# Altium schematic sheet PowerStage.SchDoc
size 431 x 279 mm; Date: Not shown in title block; ApprovedBy: Not shown in title block; CheckedBy: Not shown in title block; Author: Not shown in title block; CompanyName: Not shown in title block; DrawnBy: Forest Fu; Engineer: Not shown in title block; Organization: Not shown in title block; Address1: Not shown in title block; Address2: Not shown in title block; Address3: Not shown in title block; Address4: Not shown in title block; DocumentNumber: 1; Revision: Use project parameter SCH_Rev; SheetNumber: 2; SheetTotal: 6; PageSetup: Record=PageOptions¦CenterHorizontal=True¦CenterVertical=True¦PrintScale=1.00¦XCorrection=1.00¦YCorrection=1.00¦PrintKind=0¦BorderSize=5000000¦LeftOffset=0¦BottomOffset=0¦Orientation=2¦PaperLength=1000¦PaperWidth=1000¦Scale=100¦PaperSource=15¦PrintQuality=600¦MediaType=1¦DitherType=10¦PaperKind=Letter¦PrintScaleMode=1
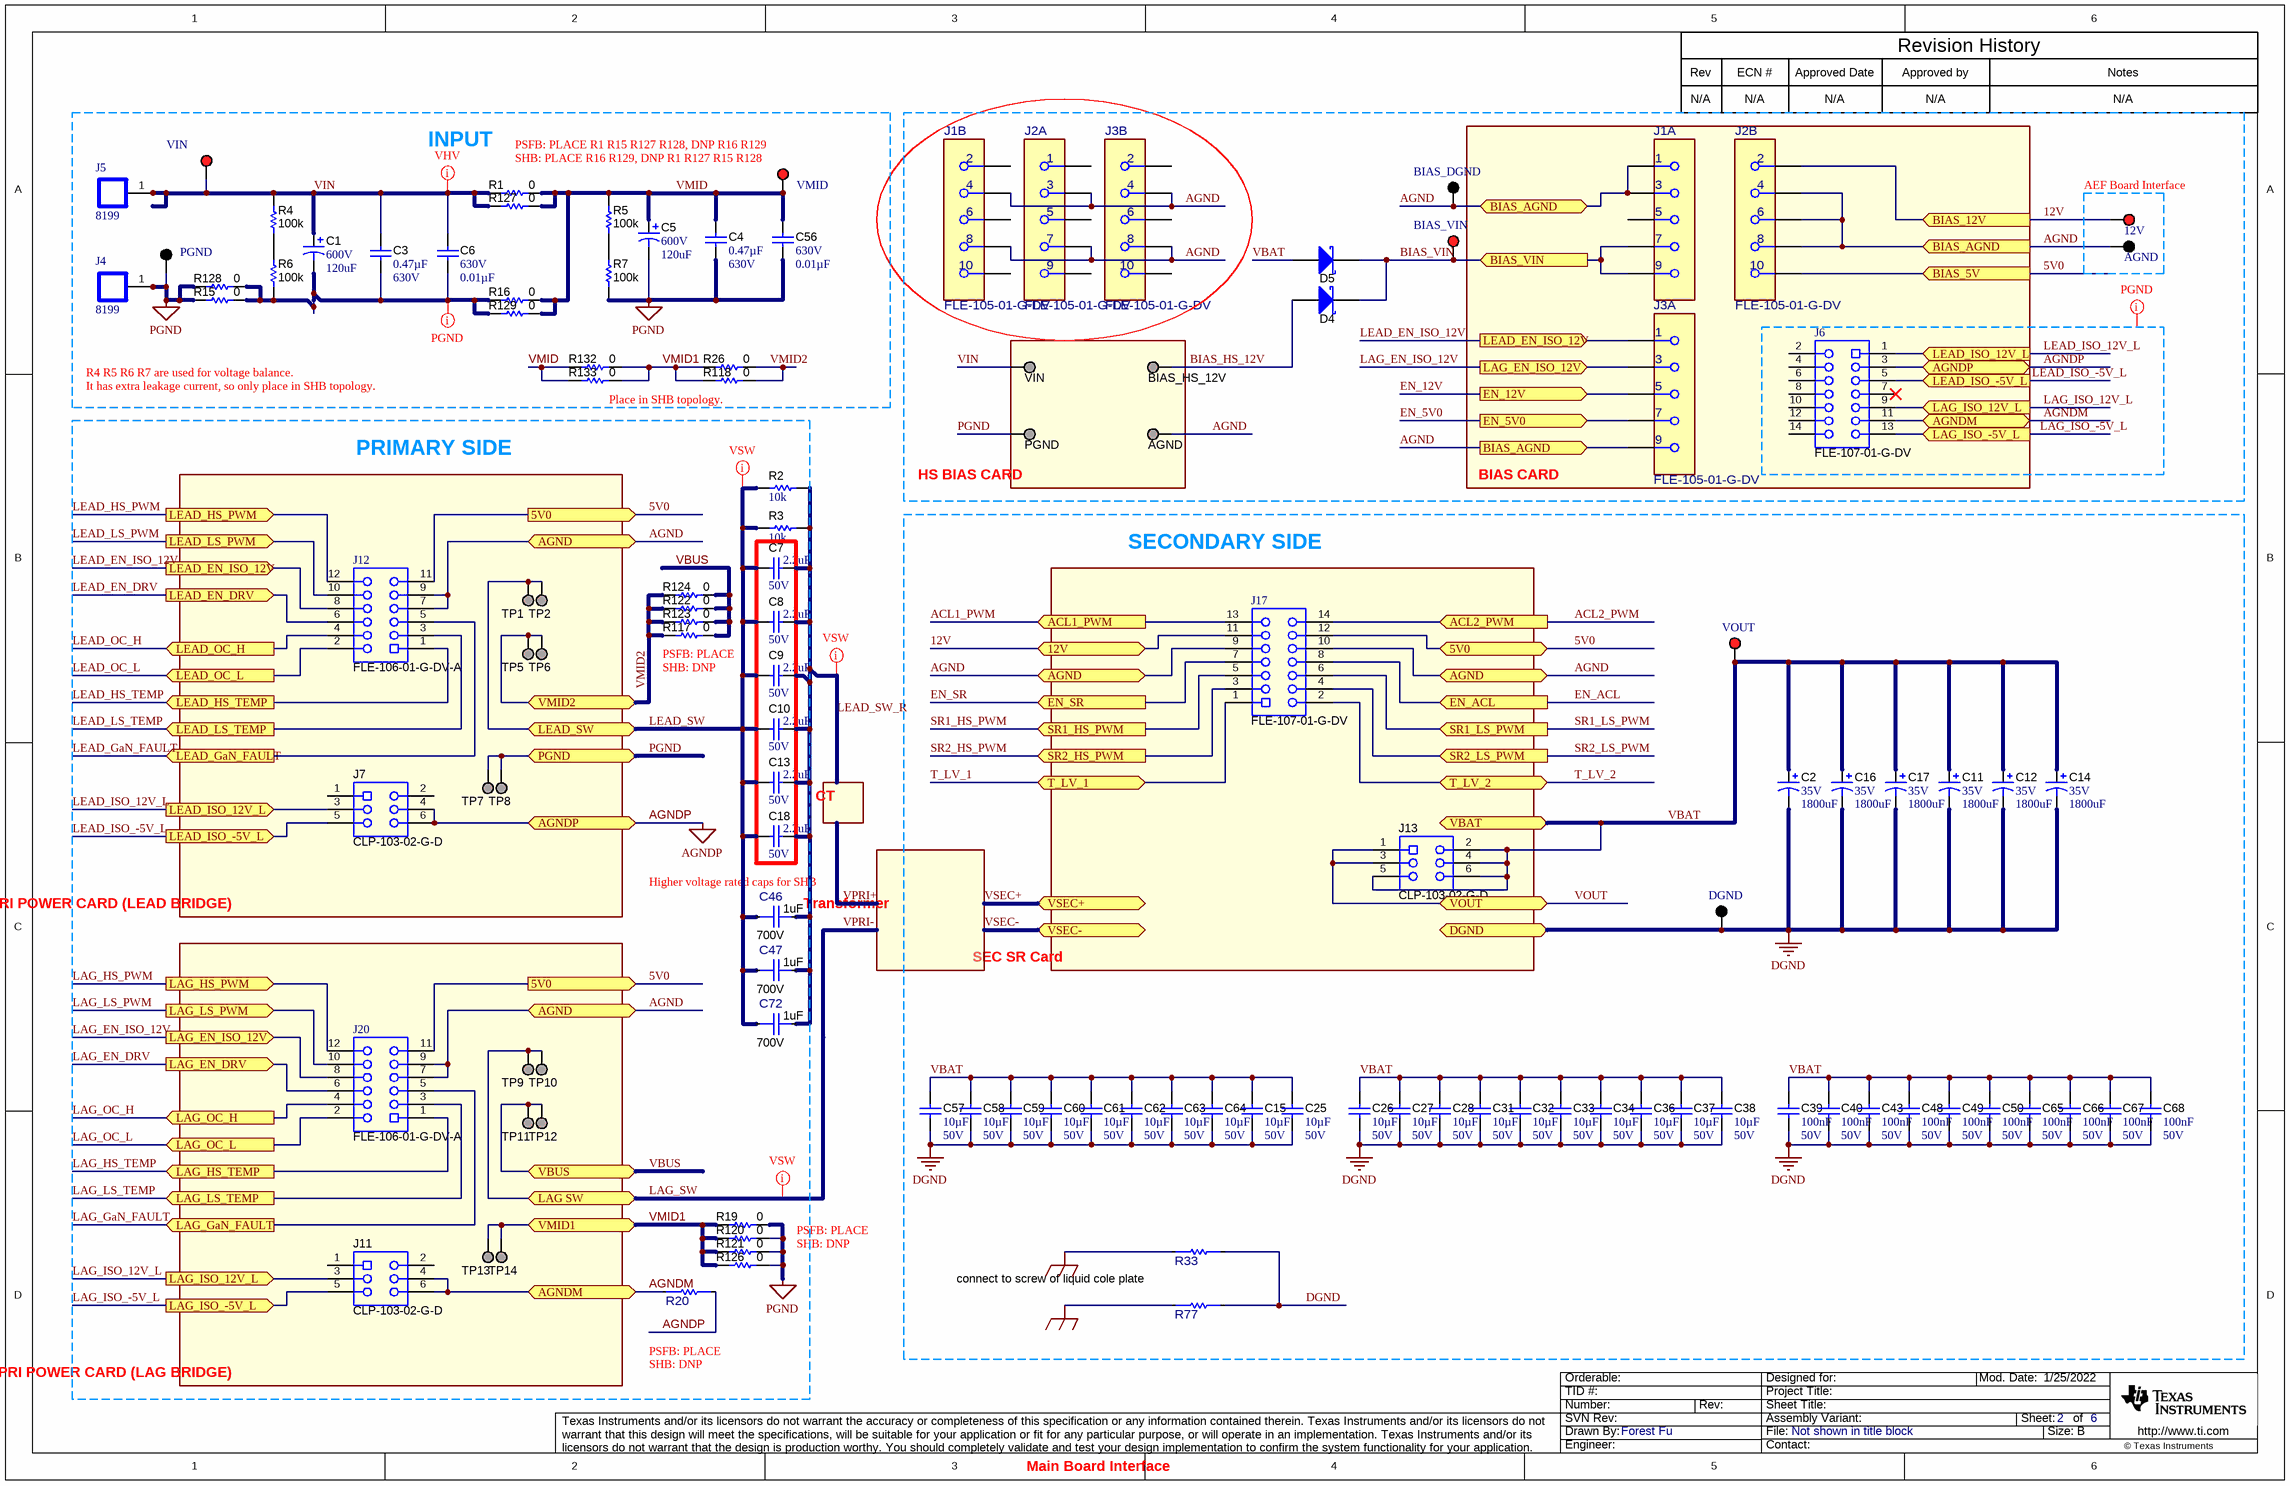
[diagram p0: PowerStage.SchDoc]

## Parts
(Parts that share a designator on the sheet are numbered #1, #2 ... from top to bottom, then left to right.)
12V  5000  [Keystone5000]  (value not drawn)
AGND#1  5001  [Keystone5001]  (value not drawn)
AGND#2  0312-0-15-15-34-27-10-0  [Mill-Max_0312-0-15-15-34-27-10-0]  (value not drawn)
BIAS_DGND  5001  [Keystone5001]  (value not drawn)
BIAS_HS_12V  0312-0-15-15-34-27-10-0  [Mill-Max_0312-0-15-15-34-27-10-0]  (value not drawn)
BIAS_VIN  5000  [Keystone5000]  (value not drawn)
C1  VDC_V: 600V  ValueDisplayed: 120uF  [Nichicon_3000x4500_Snap]  (hidden comment: LGN2X121MELB45)
C2  VDC_V: 35V  ValueDisplayed: 1800uF  [B41896_1600x3150]  (hidden comment: B41896C7188M000)
C3  ValueDisplayed: 0.47µF  VDC_V: 630V  [2220_280]  (hidden comment: CGA9P1X7T2J474M250KC)
C4  ValueDisplayed: 0.47µF  VDC_V: 630V  [2220_280]  (hidden comment: CGA9P1X7T2J474M250KC)
C5  VDC_V: 600V  ValueDisplayed: 120uF  [Nichicon_3000x4500_Snap]  (hidden comment: LGN2X121MELB45)
C6  VDC_V: 630V  ValueDisplayed: 0.01µF  [1210_150]  (hidden comment: CGA6J4C0G2J103J125AA)
C7  VDC_V: 50V  ValueDisplayed: 2.2uF  [1206_180]  (hidden comment: CGA5L3X7R1H225K160AB)
C8  VDC_V: 50V  ValueDisplayed: 2.2uF  [1206_180]  (hidden comment: CGA5L3X7R1H225K160AB)
C9  VDC_V: 50V  ValueDisplayed: 2.2uF  [1206_180]  (hidden comment: CGA5L3X7R1H225K160AB)
C10  VDC_V: 50V  ValueDisplayed: 2.2uF  [1206_180]  (hidden comment: CGA5L3X7R1H225K160AB)
C11  VDC_V: 35V  ValueDisplayed: 1800uF  [B41896_1600x3150]  (hidden comment: B41896C7188M000)
C12  VDC_V: 35V  ValueDisplayed: 1800uF  [B41896_1600x3150]  (hidden comment: B41896C7188M000)
C13  VDC_V: 50V  ValueDisplayed: 2.2uF  [1206_180]  (hidden comment: CGA5L3X7R1H225K160AB)
C14  VDC_V: 35V  ValueDisplayed: 1800uF  [B41896_1600x3150]  (hidden comment: B41896C7188M000)
C15  ValueDisplayed: 10µF  VDC_V: 50V  [1210_280]  (hidden comment: CGA6P3X7S1H106K250AE)
C16  VDC_V: 35V  ValueDisplayed: 1800uF  [B41896_1600x3150]  (hidden comment: B41896C7188M000)
C17  VDC_V: 35V  ValueDisplayed: 1800uF  [B41896_1600x3150]  (hidden comment: B41896C7188M000)
C18  VDC_V: 50V  ValueDisplayed: 2.2uF  [1206_180]  (hidden comment: CGA5L3X7R1H225K160AB)
C25  ValueDisplayed: 10µF  VDC_V: 50V  [1210_280]  (hidden comment: CGA6P3X7S1H106K250AE)
C26  ValueDisplayed: 10µF  VDC_V: 50V  [1210_280]  (hidden comment: CGA6P3X7S1H106K250AE)
C27  ValueDisplayed: 10µF  VDC_V: 50V  [1210_280]  (hidden comment: CGA6P3X7S1H106K250AE)
C28  ValueDisplayed: 10µF  VDC_V: 50V  [1210_280]  (hidden comment: CGA6P3X7S1H106K250AE)
C31  ValueDisplayed: 10µF  VDC_V: 50V  [1210_280]  (hidden comment: CGA6P3X7S1H106K250AE)
C32  ValueDisplayed: 10µF  VDC_V: 50V  [1210_280]  (hidden comment: CGA6P3X7S1H106K250AE)
C33  ValueDisplayed: 10µF  VDC_V: 50V  [1210_280]  (hidden comment: CGA6P3X7S1H106K250AE)
C34  ValueDisplayed: 10µF  VDC_V: 50V  [1210_280]  (hidden comment: CGA6P3X7S1H106K250AE)
C36  ValueDisplayed: 10µF  VDC_V: 50V  [1210_280]  (hidden comment: CGA6P3X7S1H106K250AE)
C37  ValueDisplayed: 10µF  VDC_V: 50V  [1210_280]  (hidden comment: CGA6P3X7S1H106K250AE)
C38  ValueDisplayed: 10µF  VDC_V: 50V  [1210_280]  (hidden comment: CGA6P3X7S1H106K250AE)
C39  Cap_F: 100nF  VDC_V: 50V  [0603]  (hidden comment: 06035C104KAZ2A)
C40  Cap_F: 100nF  VDC_V: 50V  [0603]  (hidden comment: 06035C104KAZ2A)
C43  Cap_F: 100nF  VDC_V: 50V  [0603]  (hidden comment: 06035C104KAZ2A)
C46  ValueDisplayed: 1uF  VDC_V: 700V  [FP-B58035U7105M052_SMD2-MFG]  (hidden comment: B58035U7105M052)
C47  ValueDisplayed: 1uF  VDC_V: 700V  [FP-B58035U7105M052_SMD2-MFG]  (hidden comment: B58035U7105M052)
C48  Cap_F: 100nF  VDC_V: 50V  [0603]  (hidden comment: 06035C104KAZ2A)
C49  Cap_F: 100nF  VDC_V: 50V  [0603]  (hidden comment: 06035C104KAZ2A)
C50  Cap_F: 100nF  VDC_V: 50V  [0603]  (hidden comment: 06035C104KAZ2A)
C56  VDC_V: 630V  ValueDisplayed: 0.01µF  [1210_150]  (hidden comment: CGA6J4C0G2J103J125AA)
C57  ValueDisplayed: 10µF  VDC_V: 50V  [1210_280]  (hidden comment: CGA6P3X7S1H106K250AE)
C58  ValueDisplayed: 10µF  VDC_V: 50V  [1210_280]  (hidden comment: CGA6P3X7S1H106K250AE)
C59  ValueDisplayed: 10µF  VDC_V: 50V  [1210_280]  (hidden comment: CGA6P3X7S1H106K250AE)
C60  ValueDisplayed: 10µF  VDC_V: 50V  [1210_280]  (hidden comment: CGA6P3X7S1H106K250AE)
C61  ValueDisplayed: 10µF  VDC_V: 50V  [1210_280]  (hidden comment: CGA6P3X7S1H106K250AE)
C62  ValueDisplayed: 10µF  VDC_V: 50V  [1210_280]  (hidden comment: CGA6P3X7S1H106K250AE)
C63  ValueDisplayed: 10µF  VDC_V: 50V  [1210_280]  (hidden comment: CGA6P3X7S1H106K250AE)
C64  ValueDisplayed: 10µF  VDC_V: 50V  [1210_280]  (hidden comment: CGA6P3X7S1H106K250AE)
C65  Cap_F: 100nF  VDC_V: 50V  [0603]  (hidden comment: 06035C104KAZ2A)
C66  Cap_F: 100nF  VDC_V: 50V  [0603]  (hidden comment: 06035C104KAZ2A)
C67  Cap_F: 100nF  VDC_V: 50V  [0603]  (hidden comment: 06035C104KAZ2A)
C68  Cap_F: 100nF  VDC_V: 50V  [0603]  (hidden comment: 06035C104KAZ2A)
C72  ValueDisplayed: 1uF  VDC_V: 700V  [FP-B58035U7105M052_SMD2-MFG]  (hidden comment: B58035U7105M052)
D4  FSV340AF  [SMAF]  (value not drawn)
D5  FSV340AF  [SMAF]  (value not drawn)
DGND  5001  [Keystone5001]  (value not drawn)
J1  FLE-105-01-G-DV  [FP-FLE-105-01-G-DV_HDR10-MFG]  (value not drawn)  (parts A,B of 2)
J2  FLE-105-01-G-DV  [FP-FLE-105-01-G-DV_HDR10-MFG]  (parts A,B of 2)
J3  FLE-105-01-G-DV  [FP-FLE-105-01-G-DV_HDR10-MFG]  (parts A,B of 2)
J4  8199  [SCREW_TERMINAL_8199]
J5  8199  [SCREW_TERMINAL_8199]
J6  FLE-107-01-G-DV  [Samtec_FLE-107-01-x-DV]
J7  CLP-103-02-G-D  [Samtec_CLP-103-02-x-D]
J11  CLP-103-02-G-D  [Samtec_CLP-103-02-x-D]
J12  FLE-106-01-G-DV-A  [Samtec_FLE-106-01-x-DV-A]
J13  CLP-103-02-G-D  [Samtec_CLP-103-02-x-D]
J17  FLE-107-01-G-DV  [Samtec_FLE-107-01-x-DV]
J20  FLE-106-01-G-DV-A  [Samtec_FLE-106-01-x-DV-A]
PGND#1  5001  [Keystone5001]  (value not drawn)
PGND#2  0312-0-15-15-34-27-10-0  [Mill-Max_0312-0-15-15-34-27-10-0]  (value not drawn)
R1  ValueDisplayed: 0  [2512]  (hidden comment: RMC1JPTE)
R2  ValueDisplayed: 10k  [1206L]  (hidden comment: CRCW120610K0JNEA)
R3  ValueDisplayed: 10k  [1206L]  (hidden comment: CRCW120610K0JNEA)
R4  ValueDisplayed: 100k  [1206]  (hidden comment: CRCW1206100KJNEA)
R5  ValueDisplayed: 100k  [1206]  (hidden comment: CRCW1206100KJNEA)
R6  ValueDisplayed: 100k  [1206]  (hidden comment: CRCW1206100KJNEA)
R7  ValueDisplayed: 100k  [1206]  (hidden comment: CRCW1206100KJNEA)
R15  ValueDisplayed: 0  [2512]  (hidden comment: RMC1JPTE)
R16  ValueDisplayed: 0  [2512]  (hidden comment: RMC1JPTE)
R19  ValueDisplayed: 0  [2512]  (hidden comment: RMC1JPTE)
R20  RMCF1206ZT0R00  [FP-RMCF1206ZT0R00_1206-MFG]  (value not drawn)
R26  ValueDisplayed: 0  [2512]  (hidden comment: RMC1JPTE)
R33  RMCF1206ZT0R00  [FP-RMCF1206ZT0R00_1206-MFG]  (value not drawn)
R77  RMCF1206ZT0R00  [FP-RMCF1206ZT0R00_1206-MFG]  (value not drawn)
R117  ValueDisplayed: 0  [2512]  (hidden comment: RMC1JPTE)
R118  ValueDisplayed: 0  [2512]  (hidden comment: RMC1JPTE)
R120  ValueDisplayed: 0  [2512]  (hidden comment: RMC1JPTE)
R121  ValueDisplayed: 0  [2512]  (hidden comment: RMC1JPTE)
R122  ValueDisplayed: 0  [2512]  (hidden comment: RMC1JPTE)
R123  ValueDisplayed: 0  [2512]  (hidden comment: RMC1JPTE)
R124  ValueDisplayed: 0  [2512]  (hidden comment: RMC1JPTE)
R126  ValueDisplayed: 0  [2512]  (hidden comment: RMC1JPTE)
R127  ValueDisplayed: 0  [2512]  (hidden comment: RMC1JPTE)
R128  ValueDisplayed: 0  [2512]  (hidden comment: RMC1JPTE)
R129  ValueDisplayed: 0  [2512]  (hidden comment: RMC1JPTE)
R132  ValueDisplayed: 0  [2512]  (hidden comment: RMC1JPTE)
R133  ValueDisplayed: 0  [2512]  (hidden comment: RMC1JPTE)
TP1  0312-0-15-15-34-27-10-0  [Mill-Max_0312-0-15-15-34-27-10-0]  (value not drawn)
TP2  0312-0-15-15-34-27-10-0  [Mill-Max_0312-0-15-15-34-27-10-0]  (value not drawn)
TP5  0312-0-15-15-34-27-10-0  [Mill-Max_0312-0-15-15-34-27-10-0]  (value not drawn)
TP6  0312-0-15-15-34-27-10-0  [Mill-Max_0312-0-15-15-34-27-10-0]  (value not drawn)
TP7  0312-0-15-15-34-27-10-0  [Mill-Max_0312-0-15-15-34-27-10-0]  (value not drawn)
TP8  0312-0-15-15-34-27-10-0  [Mill-Max_0312-0-15-15-34-27-10-0]  (value not drawn)
TP9  0312-0-15-15-34-27-10-0  [Mill-Max_0312-0-15-15-34-27-10-0]  (value not drawn)
TP10  0312-0-15-15-34-27-10-0  [Mill-Max_0312-0-15-15-34-27-10-0]  (value not drawn)
TP11  0312-0-15-15-34-27-10-0  [Mill-Max_0312-0-15-15-34-27-10-0]  (value not drawn)
TP12  0312-0-15-15-34-27-10-0  [Mill-Max_0312-0-15-15-34-27-10-0]  (value not drawn)
TP13  0312-0-15-15-34-27-10-0  [Mill-Max_0312-0-15-15-34-27-10-0]  (value not drawn)
TP14  0312-0-15-15-34-27-10-0  [Mill-Max_0312-0-15-15-34-27-10-0]  (value not drawn)
VIN#1  5000  [Keystone5000]  (value not drawn)
VIN#2  0312-0-15-15-34-27-10-0  [Mill-Max_0312-0-15-15-34-27-10-0]  (value not drawn)
VMID  5000  [Keystone5000]  (value not drawn)
VOUT  5000  [Keystone5000]  (value not drawn)

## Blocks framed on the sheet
BIAS CARD: J1-J3 J6
HS BIAS CARD: AGND#2 BIAS_HS_12V PGND#2 VIN#2
PRI POWER CARD (LEAD BRIDGE): J7 J12 TP1 TP2 TP5-TP8
SEC SR Card: J13 J17
PRI POWER CARD (LAG BRIDGE): J11 J20 TP9-TP14

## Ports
5V0 (bidir), 5V0 (out), 12V (bidir), ACL1_PWM (in), ACL2_PWM (in), AGND (bidir), AGNDM (bidir), AGNDP (bidir), BIAS_5V (in), BIAS_12V (in), BIAS_AGND (bidir), BIAS_AGND (in), BIAS_AGND (out), BIAS_VIN (in), DGND (bidir), EN_5V0 (out), EN_12V (out), EN_ACL (in), EN_SR (in), LAG SW (bidir), LAG_EN_DRV (out), LAG_EN_ISO_12V (out), LAG_GaN_FAULT (in), LAG_HS_PWM (out), LAG_HS_TEMP (in), LAG_ISO_12V_L (in), LAG_ISO_12V_L (out), LAG_ISO_-5V_L (in), LAG_ISO_-5V_L (out), LAG_LS_PWM (out), LAG_LS_TEMP (in), LAG_OC_H (in), LAG_OC_L (in), LEAD_EN_DRV (out), LEAD_EN_ISO_12V (out), LEAD_GaN_FAULT (in), LEAD_HS_PWM (out), LEAD_HS_TEMP (in), LEAD_ISO_12V_L (in), LEAD_ISO_12V_L (out), LEAD_ISO_-5V_L (in), LEAD_ISO_-5V_L (out), LEAD_LS_PWM (out), LEAD_LS_TEMP (in), LEAD_OC_H (in), LEAD_OC_L (in), LEAD_SW (bidir), PGND (bidir), SR1_HS_PWM (in), SR1_LS_PWM (in), SR2_HS_PWM (in), SR2_LS_PWM (in), T_LV_1 (bidir), T_LV_2 (bidir), VBAT (bidir), VBUS (bidir), VMID1 (bidir), VMID2 (bidir), VOUT (bidir), VSEC+ (bidir), VSEC- (bidir)

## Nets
AGNDP: J6.3 J7.4 J7.6 R20.2 ; port AGNDP
DGND: C2.2(-) C11.2(-) C12.2(-) C14.2(-) C15.2 C16.2(-) C17.2(-) C25.2 C26.2 C27.2 C28.2 C31.2 C32.2 C33.2 C34.2 C36.2 C37.2 C38.2 C39.2 C40.2 C43.2 C48.2 C49.2 C50.2 C57.2 C58.2 C59.2 C60.2 C61.2 C62.2 C63.2 C64.2 C65.2 C66.2 C67.2 C68.2 DGND.1 R33.2 R77.2 ; port DGND
PGND: C4.2 C5.2(-) C56.2 J4.1 J4.2 J4.3 J4.4 J4.5 J4.6 PGND#1.1 PGND#2.1 R7.1 R15.1 R19.2 R120.2 R121.2 R126.2 R128.1 TP7.1 TP8.1 ; port PGND
SHIELD_GND1: R33.1
SHIELD_GND2: R77.1
5V0: J2.10 J12.11 J17.12 J20.11 ; port 5V0, port BIAS_5V
12V: 12V.1 J2.2 J17.11 ; port BIAS_12V, port 12V
ACL1_PWM: J17.13 ; port ACL1_PWM
ACL2_PWM: J17.14 ; port ACL2_PWM
AGND: AGND#1.1 AGND#2.1 BIAS_DGND.1 J1.1 J1.3 J1.4 J1.8 J2.3 J2.4 J2.6 J2.7 J2.8 J3.4 J3.8 J3.9 J12.7 J12.9 J17.9 J17.10 J20.7 J20.9 ; port AGND, port BIAS_AGND
AGNDM: J6.11 J11.4 J11.6 R20.1 ; port AGNDM
BIAS_HS_12V: BIAS_HS_12V.1 D4.2(A)
BIAS_VIN: BIAS_VIN.1 D4.1(K) D5.1(K) J1.7 J1.9 ; port BIAS_VIN
EN_5V0: J3.7 ; port EN_5V0
EN_12V: J3.5 ; port EN_12V
EN_ACL: J17.8 ; port EN_ACL
EN_SR: J17.7 ; port EN_SR
LAG_EN_DRV: J20.6 ; port LAG_EN_DRV
LAG_EN_ISO_12V: J3.3 J20.8 ; port LAG_EN_ISO_12V
LAG_GaN_FAULT: J20.5 ; port LAG_GaN_FAULT
LAG_HS_PWM: J20.12 ; port LAG_HS_PWM
LAG_HS_TEMP: J20.1 ; port LAG_HS_TEMP
LAG_ISO_12V_L: J6.9 J11.3 ; port LAG_ISO_12V_L
LAG_ISO_-5V_L: J6.13 J11.5 ; port LAG_ISO_-5V_L
LAG_LS_PWM: J20.10 ; port LAG_LS_PWM
LAG_LS_TEMP: J20.3 ; port LAG_LS_TEMP
LAG_OC_H: J20.4 ; port LAG_OC_H
LAG_OC_L: J20.2 ; port LAG_OC_L
LAG_SW: TP9.1 TP10.1 ; port LAG SW  [also labelled VPRI-]
LEAD_EN_DRV: J12.6 ; port LEAD_EN_DRV
LEAD_EN_ISO_12V: J3.1 J12.8 ; port LEAD_EN_ISO_12V
LEAD_GaN_FAULT: J12.5 ; port LEAD_GaN_FAULT
LEAD_HS_PWM: J12.12 ; port LEAD_HS_PWM
LEAD_HS_TEMP: J12.1 ; port LEAD_HS_TEMP
LEAD_ISO_12V_L: J6.1 J7.3 ; port LEAD_ISO_12V_L
LEAD_ISO_-5V_L: J6.5 J7.5 ; port LEAD_ISO_-5V_L
LEAD_LS_PWM: J12.10 ; port LEAD_LS_PWM
LEAD_LS_TEMP: J12.3 ; port LEAD_LS_TEMP
LEAD_OC_H: J12.4 ; port LEAD_OC_H
LEAD_OC_L: J12.2 ; port LEAD_OC_L
LEAD_SW: C7.2 C8.2 C9.2 C10.2 C13.2 C18.2 C46.1 C47.1 C72.1 R2.1 R3.1 TP1.1 TP2.1 ; port LEAD_SW
LEAD_SW_R: C7.1 C8.1 C9.1 C10.1 C13.1 C18.1 C46.2 C47.2 C72.2 R2.2 R3.2
SR1_HS_PWM: J17.5 ; port SR1_HS_PWM
SR1_LS_PWM: J17.6 ; port SR1_LS_PWM
SR2_HS_PWM: J17.3 ; port SR2_HS_PWM
SR2_LS_PWM: J17.4 ; port SR2_LS_PWM
T_LV_1: J17.1 ; port T_LV_1
T_LV_2: J17.2 ; port T_LV_2
VBAT: C2.1(+) C11.1(+) C12.1(+) C14.1(+) C15.1 C16.1(+) C17.1(+) C25.1 C26.1 C27.1 C28.1 C31.1 C32.1 C33.1 C34.1 C36.1 C37.1 C38.1 C39.1 C40.1 C43.1 C48.1 C49.1 C50.1 C57.1 C58.1 C59.1 C60.1 C61.1 C62.1 C63.1 C64.1 C65.1 C66.1 C67.1 C68.1 D5.2(A) J13.2 J13.4 J13.5 J13.6 VOUT.1 ; port VBAT
VBUS: R117.2 R122.2 R123.2 R124.2 TP11.1 TP12.1 ; port VBUS
VIN: C1.1(+) C3.1 C6.1 J5.1 J5.2 J5.3 J5.4 J5.5 J5.6 R1.1 R4.2 R127.1 VIN#1.1 VIN#2.1
VMID: C4.1 C5.1(+) C56.1 R1.2 R5.2 R16.2 R127.2 R129.2 R132.1 R133.1 VMID.1
VMID1: R19.1 R26.1 R118.1 R120.1 R121.1 R126.1 R132.2 R133.2 TP13.1 TP14.1 ; port VMID1
VMID2: R26.2 R117.1 R118.2 R122.1 R123.1 R124.1 TP5.1 TP6.1 ; port VMID2
VOUT: J13.1 J13.3 ; port VOUT
NetC1_2: C1.2(-) C3.2 C6.2 R6.1 R15.2 R16.1 R128.2 R129.1
NetR4_1: R4.1 R6.2
NetR5_1: R5.1 R7.2

Not connected (* = marked no-connect by the designer): J1 2 5 6 10; J2 1 5 9; J3 2 6 10; J6 2 4 6 7* 8 10 12 14; J7 1 2; J11 1 2

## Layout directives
net class VHV: VIN
net class PGND: AGNDM, AGNDP, LAG_ISO_12V_L, LAG_ISO_-5V_L, LEAD_ISO_12V_L, LEAD_ISO_-5V_L, NetC1_2
net class VSW: LAG_SW, LEAD_SW, LEAD_SW_R

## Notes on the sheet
- Rev
- N/A
- ECN #
- Approved Date
- Approved by
- Revision History
- Notes
- INPUT
- PSFB: PLACE R1 R15 R127 R128, DNP R16 R129
- SHB: PLACE R16 R129, DNP R1 R127 R15 R128
- (near 12V) AEF Board Interface
- It has extra leakage current, so only place in SHB topology.
- R4 R5 R6 R7 are used for voltage balance.
- Place in SHB topology.
- PRIMARY SIDE
- SECONDARY SIDE
- (near R117) PSFB: PLACE
- SHB: DNP
- CT
- Higher voltage rated caps for SHB
- Transformer
- PSFB: PLACE
- connect to screw of liquid cole plate
- Main Board Interface

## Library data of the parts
12V BIAS_VIN VIN#1 VMID VOUT = CMP-0055137-2: Test Point, Miniature, Red, TH; Manufacturer: Keystone Electronics; Green_REACh: Passed; Green_Lifecycle: Active; ContactFinish: Silver; CNHeader: FALSE; CT: TRUE
AGND#1 BIAS_DGND DGND PGND#1 = CMP-0055138-2: Test Point, Miniature, Black, TH; Manufacturer: Keystone Electronics; ContactFinish: Silver; CNHeader: FALSE; Green_Lifecycle: Active; Green_REACh: Passed; CT: TRUE
AGND#2 BIAS_HS_12V PGND#2 TP1 TP2 TP5-TP14 VIN#2 = CMP-0055026-1: Pin Receptacle, .032-.046" .075" Dia, Gold, TH; Manufacturer: Mill-Max; CNHeader: FALSE; Green_Lifecycle: Active; Gender: Female; Green_REACh: Passed
C1 C5 = CMP-0010058-3: CAP, AL, 120 uF, 600 V, +/- 20%, TH; Manufacturer: Nichicon; TaMin_C: -25°C; Polarized: Y; SizeAreaWB_mm2: 1024; Value1: Unknown; U/M: EA; Value: 120uF; TaMax_C: 105°C; SizeZ_mm: 47; SizeX_mm: 30; Cap_Case: 30x45mm; SizeArea_mm2: 900; CompType: Capacitor; AEC Qualified: N; Cap_F: 120µF; IRMS_A: 7.4dA; AEC Category: Q200
C2 C11 C12 C14 C16 C17 = CMP-0010311-2: CAP, AL, 1800 uF, 35 V, +/- 20%, 0.023 ohm, AEC-Q200 Grade 1, TH; Manufacturer: TDK; TaMin_C: -55°C; ESR_ohm: 0.023; Polarized: Y; SizeAreaWB_mm2: 324; U/M: EA; Value: 1800uF; TaMax_C: 125°C; SizeZ_mm: 33.5; SizeX_mm: 16; Cap_Case: 16x31.5mm; SizeArea_mm2: 256; CompType: Capacitor; Cap_F: 1.8mF; IRMS_A: 3.16A; AEC Grade: 1; AEC Category: Q200
C3 C4 = CMP-0860865-1: CAP, CERM, 0.47 µF, 630 V,+/- 20%, X7T, AEC-Q200 Grade 1, 2220; Manufacturer: TDK; SizeZ_mm: 2.8; SizeY_mm: 5; AEC Qualified: Y; Cap_Case: 2220; Polarized: N; SizeArea_mm2: 28.5; U/M: EA; AEC Grade: 1; AEC Category: Q200; TaMax_C: 125°C; TaMin_C: -55°C; Cap_F: 470nF; SizeAreaWB_mm2: 53.9; SizeX_mm: 5.7; Value: 0.47uF
C6 C56 = CMP-0860380-1: CAP, CERM, 0.01 µF, 630 V,+/- 5%, C0G/NP0, AEC-Q200 Grade 1, 1210; Manufacturer: TDK; AEC Qualified: Y; Polarized: N; SizeZ_mm: 1.5; SizeArea_mm2: 8; U/M: EA; SizeX_mm: 3.2; SizeY_mm: 2.5; Cap_F: 10nF; SizeAreaWB_mm2: 14.7; TaMin_C: -55°C; Cap_Case: 1210; Value: 0.01uF; AEC Grade: 1; TaMax_C: 125°C; AEC Category: Q200
C7-C10 C13 C18 = CMP-0008788-2: CAP, CERM, 2.2 uF, 50 V, +/- 10%, X7R, AEC-Q200 Grade 1, 1206; Manufacturer: TDK; TaMin_C: -55°C; ESR_ohm: 5.887m; Polarized: N; SizeAreaWB_mm2: 10.92; Value1: 0.005887 ohm; U/M: EA; Value: 2.2uF; TaMax_C: 125°C; SizeZ_mm: 1.8; SizeX_mm: 3.2; SizeY_mm: 1.6; SizeArea_mm2: 5.12; AEC Qualified: Y; Cap_F: 2.2µF; IRMS_A: 2.99226A; AEC Grade: 1; AEC Category: Q200
C15 C25-C28 C31-C34 C36-C38 C57-C64 = CMP-0085350-1: CAP, CERM, 10 µF, 50 V,+/- 10%, X7S, AEC-Q200 Grade 1, 1210; Manufacturer: TDK; SizeZ_mm: 2.8; SizeY_mm: 2.5; SizeAreaWB_mm2: 14.7; AEC Qualified: Y; SizeArea_mm2: 8; U/M: EA; Value: 10uF; Polarized: N; TaMax_C: 125°C; SizeX_mm: 3.2; Cap_Case: 1210; TaMin_C: -55°C; AEC Grade: 1; AEC Category: Q200
C39 C40 C43 C48-C50 C65-C68 = CMP-0079095-1: CAP, CERM, 0.1 µF, 50 V,+/- 10%, X7R, AEC-Q200 Grade 1, 0603; Manufacturer: AVX; SizeAreaWB_mm2: 4.68; SizeArea_mm2: 1.28; AEC Qualified: Y; AEC Category: Q200; Value: 0.1uF; TaMax_C: 125°C; SizeZ_mm: 1; Polarized: N; TaMin_C: -55°C; SizeY_mm: 0.8; U/M: EA; SizeX_mm: 1.6; ValueDisplayed: 0.1µF
C46 C47 C72 = CMP-0124726-1: 1 µF ±20% 700V Ceramic Capacitor Stacked SMD, 4 J-Lead; Manufacturer: TDK; AEC Grade: Grade 0; AEC Qualified: Yes; Cap_F: 1µF; SizeZ_mm: 9.6mm; Value: 1µF
D4 D5 = CMP-0028855-2: Diode, Schottky, 40 V, 3 A, AEC-Q101, SMAF; Manufacturer: Fairchild Semiconductor; Value1: 3A; SizeArea_mm2: 11.75; SizeZ_mm: 1; TJmax_C: 150°C; Vr_V: 40V; SizeX_mm: 4.7; AEC Qualified: Y; SizeY_mm: 2.5; Value2: 0.5V; AEC Category: Q101; Vf_V: 500mV; Value: 40V; Green_REACh: Incomplete; SizeAreaWB_mm2: 19.95; Green_Lifecycle: Not Set
J1-J3 = CMP-0088850-1: 10 Position Receptacle Connector  Surface Mount; Manufacturer: SAMTEC; ContactFinish: Gold,Nickel; Current_A: 2.9A; Is Female: yes; AEC Qualified: No; Standoff Height: 0.18mm; Conn Orientation: Vertical; Conn Gender: Female; SizeZ_mm: 4.68mm; Row_Count: 2; DUT-Pitch_mm: 1.27mm
J4 J5 = CMP-0055125-1: TERMINAL SCREW PC 30AMP, TH; Manufacturer: Keystone; CNHeader: FALSE; Green_Lifecycle: Active; Green_REACh: Passed; CompType: Screw Connector
J6 J17 = CMP-0075566-1: Receptacle, 1.27mm, 7x2, Gold, SMT; Manufacturer: Samtec; Pitch_mm: 1.27; Gender: Female; CT: True; Row_Count: 2; CompType: Socket Strip; CNHeader: False
J7 J11 J13 = CMP-0055704-1: Receptacle, 1.27mm, 3x2, Gold, SMT; Manufacturer: Samtec; CNHeader: FALSE; Current_A: 3.3A; Gender: Female; Voltage_V: 240V; CompType: Socket Strip; Row_Count: 2; RowSpacing_mm: 1.27; CT: TRUE; Cert_UL: Y
J12 J20 = CMP-0075577-1: Receptacle, 1.27mm, 6x2, Gold, SMT; Manufacturer: Samtec; Pitch_mm: 1.27; Gender: Female; Cert_CSA: Y; Current_A: 2A; CT: True; Row_Count: 2; CompType: Socket Strip; CNHeader: False
R1 R15 R16 R19 R26 R117 R118 R120-R124 R126-R129 R132 R133 = CMP-0080698-1: RES, 0, 0%, 1 W, AEC-Q200 Grade 0, 2512; Manufacturer: Kamaya; SizeAreaWB_mm2: 43.16; SizeArea_mm2: 20.16; AEC Qualified: Y; AEC Category: Q200; Value: 0; SizeZ_mm: 0.71; SizeY_mm: 3.2; Power_W: 1W; SizeX_mm: 6.3
R2 R3 = CMP-0018576-3: RES, 10 k, 5%, 0.25 W, AEC-Q200 Grade 0, 1206; Manufacturer: Vishay-Dale; Power_W: 250mW; TempCo: 200 ppm/C; Value_Code: 10k0; Value: 10k; EIA_Code: E24; SizeX_mm: 3.2; SizeY_mm: 1.6; SizeZ_mm: 1.35; Value2: 0.25W; SizeArea_mm2: 5.12; AEC Qualified: Y; VDC_V: 200V; AEC Category: Q200; AEC Grade: 0
R4-R7 = CMP-0018574-3: RES, 100 k, 5%, 0.25 W, AEC-Q200 Grade 0, 1206; Manufacturer: Vishay-Dale; Power_W: 250mW; TempCo: 200 ppm/C; Value: 100k; EIA_Code: E24; SizeX_mm: 3.2; SizeY_mm: 1.6; SizeZ_mm: 1.35; Value2: 0.25W; SizeArea_mm2: 5.12; AEC Qualified: Y; VDC_V: 200V; AEC Category: Q200; AEC Grade: 0
R20 R33 R77 = CMP-0093609-1: 0Ω ±0 0.25W 1206 Thick Film Chip Resistor AEC-Q200 compliant; Manufacturer: Stackpole Electronics; Res_ohm: 0; AEC Qualified: Yes; Value: 0; VDC_V: 200V; AEC Grade: Grade 0; Power_W: 250mW; SizeZ_mm: 0.7mm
